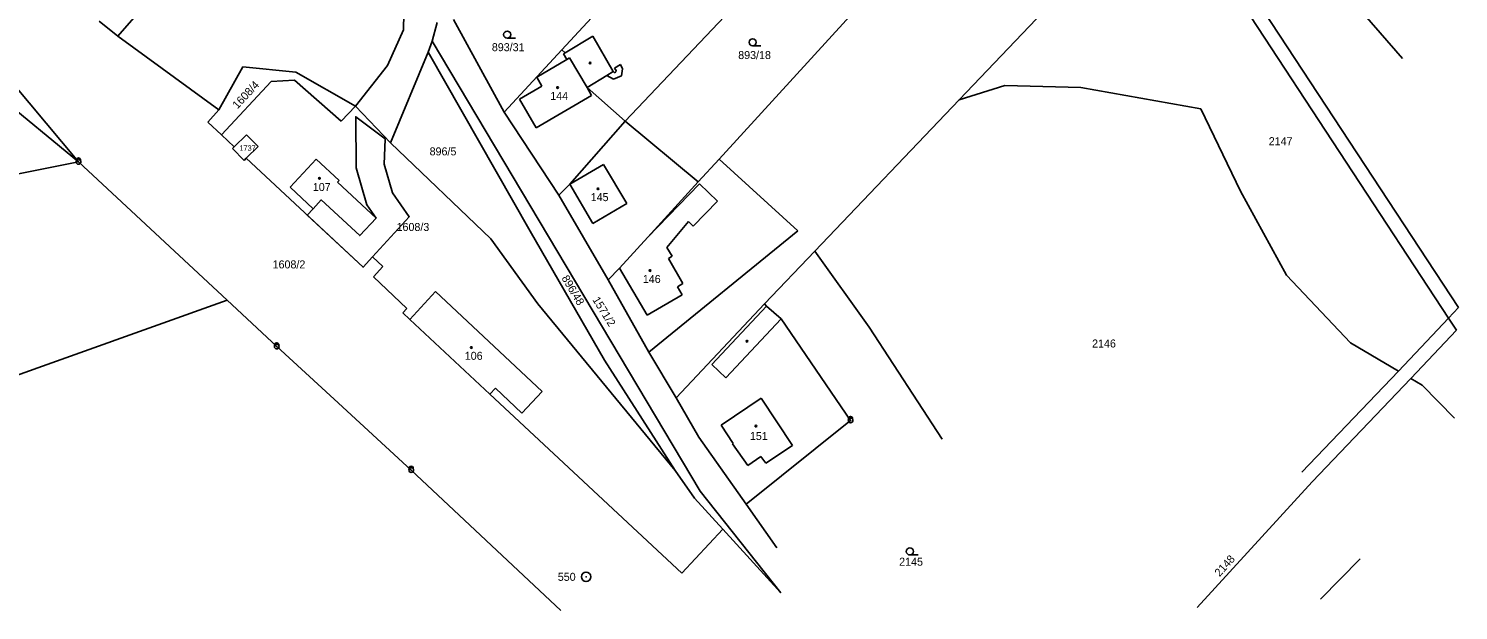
# Model space of a CAD drawing. Extents: x -801826 to -800592, y -1032871 to -1031813.
# Drawn here: x -800902.2 to -800598.5, y -1032871.4 to -1032747.9 of the extents above; entities that cross this region are included whole.
import ezdxf

# ---------------------------------------------------------------- set-up
doc = ezdxf.new("R2010")
doc.units = 0
for name, color, linetype in [('Vrstva 1', 7, 'Continuous'), ('Vrstva 17', 7, 'Continuous'), ('Vrstva 18', 7, 'Continuous'), ('Vrstva 19', 7, 'Continuous'), ('Vrstva 24', 7, 'Continuous'), ('Vrstva 25', 7, 'Continuous'), ('Vrstva 27', 7, 'Continuous'), ('Vrstva 4', 7, 'Continuous')]:
    doc.layers.add(name, color=color, linetype=linetype)

msp = doc.modelspace()

# ---------------------------------------------------------------- linework, layer by layer
at = {"layer": 'Vrstva 1'}
for p, q in [((-800685.05, -1032668.07), (-800610.32, -1032754.24)), ((-800974.29, -1032708.2), (-800891.58, -1032776.17)), ((-800891.58, -1032776.17), (-800936.91, -1032722.01)), ((-800704.52, -1032763.01), (-800666.33, -1032723)), ((-800862.89, -1032726), (-800883.21, -1032749.46)), ((-800775.49, -1032767.53), (-800739.93, -1032730.06)), ((-800822.52, -1032748.12), (-800822.34, -1032737.75)), ((-800719.34, -1032735.97), (-800755.52, -1032775.59)), ((-800598.47, -1032807.13), (-800641.5, -1032741.52)), ((-800779.9, -1032742.67), (-800788.9, -1032752.39)), ((-800600.58, -1032809.38), (-800644.04, -1032743.12)), ((-800883.21, -1032749.46), (-800887.16, -1032746.32)), ((-800816.49, -1032750.53), (-800815.39, -1032746.59)), ((-800801.15, -1032765.61), (-800811.93, -1032745.91)), ((-800883.21, -1032749.46), (-800861.74, -1032765.15)), ((-800825.94, -1032755.74), (-800822.52, -1032748.12)), ((-800817.28, -1032752.88), (-800816.49, -1032750.53)), ((-800759.53, -1032846.08), (-800816.49, -1032750.53)), ((-800788.23, -1032753.03), (-800782.33, -1032749.51)), ((-800782.33, -1032749.51), (-800778, -1032756.99)), ((-800825.32, -1032772.12), (-800817.28, -1032752.88)), ((-800795.62, -1032790.87), (-800817.28, -1032752.88)), ((-800788.9, -1032752.39), (-800801.15, -1032765.61)), ((-800788.23, -1032753.03), (-800788.9, -1032752.39)), ((-800861.74, -1032765.15), (-800856.65, -1032755.96)), ((-800856.65, -1032755.96), (-800845.4, -1032757.1)), ((-800832.71, -1032764.32), (-800825.94, -1032755.74)), ((-800776.46, -1032755.5), (-800777.71, -1032756.24)), ((-800777.71, -1032756.24), (-800777.39, -1032756.79)), ((-800776.02, -1032756.45), (-800776.46, -1032755.5)), ((-800776.25, -1032757.88), (-800776.02, -1032756.45)), ((-800861.23, -1032770.42), (-800850.67, -1032759.09)), ((-800850.67, -1032759.09), (-800845.69, -1032758.85)), ((-800845.69, -1032758.85), (-800835.76, -1032767.56)), ((-800845.4, -1032757.1), (-800832.71, -1032764.32)), ((-800783.54, -1032760.36), (-800779.32, -1032757.8)), ((-800779.32, -1032757.8), (-800777.91, -1032758.6)), ((-800777.72, -1032757.25), (-800778, -1032756.99)), ((-800777.91, -1032758.6), (-800776.25, -1032757.88)), ((-800777.41, -1032757.08), (-800777.72, -1032757.25)), ((-800777.39, -1032756.79), (-800777.41, -1032757.08)), ((-800775.49, -1032767.53), (-800783.54, -1032760.36)), ((-800694.83, -1032759.95), (-800704.52, -1032763.01)), ((-800678.69, -1032760.36), (-800694.83, -1032759.95)), ((-800653.15, -1032764.9), (-800678.69, -1032760.36)), ((-800861.74, -1032765.15), (-800864.13, -1032767.71)), ((-800835.76, -1032767.56), (-800832.71, -1032764.32)), ((-800832.71, -1032764.32), (-800825.32, -1032772.12)), ((-800801.15, -1032765.61), (-800789.53, -1032783.23)), ((-800735.19, -1032795.14), (-800704.52, -1032763.01)), ((-800644.79, -1032782.39), (-800653.15, -1032764.9)), ((-800864.13, -1032767.71), (-800861.23, -1032770.42)), ((-800787.2, -1032780.94), (-800775.49, -1032767.53)), ((-800759.94, -1032780.44), (-800775.49, -1032767.53)), ((-800861.23, -1032770.42), (-800858.49, -1032772.99)), ((-800858.49, -1032772.99), (-800855.86, -1032770.41)), ((-800853.41, -1032772.91), (-800855.86, -1032770.41)), ((-800858.86, -1032773.35), (-800858.49, -1032772.99)), ((-800858.86, -1032773.35), (-800856.41, -1032775.85)), ((-800853.41, -1032772.91), (-800855.93, -1032775.38)), ((-800825.32, -1032772.12), (-800803.96, -1032792.55)), ((-800891.58, -1032776.17), (-800918.55, -1032781.54)), ((-800891.58, -1032776.17), (-800860.02, -1032805.58)), ((-800855.93, -1032775.38), (-800856.41, -1032775.85)), ((-800855.93, -1032775.38), (-800831.14, -1032798.57)), ((-800846.61, -1032781.52), (-800841.09, -1032775.58)), ((-800836.18, -1032780.12), (-800841.09, -1032775.58)), ((-800755.52, -1032775.59), (-800759.94, -1032780.44)), ((-800738.81, -1032790.85), (-800755.52, -1032775.59)), ((-800836.53, -1032780.5), (-800836.18, -1032780.12)), ((-800828.38, -1032788.14), (-800836.53, -1032780.5)), ((-800789.53, -1032783.23), (-800787.2, -1032780.94)), ((-800770.63, -1032792.16), (-800759.94, -1032780.44)), ((-800846.61, -1032781.52), (-800841.71, -1032786.12)), ((-800779.08, -1032801.22), (-800789.53, -1032783.23)), ((-800634.97, -1032800.21), (-800644.79, -1032782.39)), ((-800841.71, -1032786.12), (-800840.04, -1032784.27)), ((-800840.04, -1032784.27), (-800831.83, -1032791.83)), ((-800831.83, -1032791.83), (-800828.38, -1032788.14)), ((-800803.96, -1032792.55), (-800794.02, -1032806.35)), ((-800779.82, -1032818.29), (-800795.62, -1032790.87)), ((-800776.64, -1032798.73), (-800770.63, -1032792.16)), ((-800770.44, -1032816.58), (-800738.81, -1032790.85)), ((-800745.85, -1032806.31), (-800735.19, -1032795.14)), ((-800723.65, -1032811.31), (-800735.19, -1032795.14)), ((-800831.14, -1032798.57), (-800829.12, -1032796.36)), ((-800829.12, -1032796.36), (-800826.93, -1032798.41)), ((-800826.93, -1032798.41), (-800828.95, -1032800.62)), ((-800776.64, -1032798.73), (-800779.08, -1032801.22)), ((-800828.95, -1032800.62), (-800821.81, -1032807.31)), ((-800779.08, -1032801.22), (-800770.44, -1032816.58)), ((-800621.36, -1032814.6), (-800634.97, -1032800.21)), ((-800815.75, -1032803.7), (-800821.22, -1032809.62)), ((-800815.75, -1032803.7), (-800793.1, -1032824.93)), ((-800860.02, -1032805.58), (-801002.86, -1032856.61)), ((-800860.02, -1032805.58), (-800849.48, -1032815.4)), ((-800821.81, -1032807.31), (-800822.69, -1032808.25)), ((-800822.69, -1032808.25), (-800821.22, -1032809.62)), ((-800794.02, -1032806.35), (-800764.86, -1032841.71)), ((-800745.85, -1032806.31), (-800764.65, -1032826.32)), ((-800745.41, -1032806.81), (-800745.85, -1032806.31)), ((-800742.33, -1032809.53), (-800745.41, -1032806.81)), ((-800600.58, -1032809.38), (-800598.47, -1032807.13)), ((-800821.22, -1032809.62), (-800804.24, -1032825.48)), ((-800727.58, -1032831.07), (-800742.33, -1032809.53)), ((-800708.13, -1032835.06), (-800723.65, -1032811.31)), ((-800605.22, -1032814.32), (-800600.58, -1032809.38)), ((-800598.87, -1032811.95), (-800600.58, -1032809.38)), ((-800611.2, -1032820.59), (-800605.22, -1032814.32)), ((-800608.56, -1032822.15), (-800598.87, -1032811.95)), ((-800849.48, -1032815.4), (-800837.28, -1032826.6)), ((-800764.65, -1032826.32), (-800770.44, -1032816.58)), ((-800611.2, -1032820.59), (-800621.36, -1032814.6)), ((-800764.86, -1032841.71), (-800779.82, -1032818.29)), ((-800631.71, -1032842.08), (-800611.2, -1032820.59)), ((-800629.52, -1032844.13), (-800608.56, -1032822.15)), ((-800606.15, -1032823.57), (-800608.56, -1032822.15)), ((-800804.24, -1032825.48), (-800803.03, -1032824.25)), ((-800804.24, -1032825.48), (-800763.43, -1032863.52)), ((-800797.41, -1032829.54), (-800803.03, -1032824.25)), ((-800793.1, -1032824.93), (-800797.41, -1032829.54)), ((-800759.81, -1032834.67), (-800764.65, -1032826.32)), ((-800599.28, -1032830.62), (-800606.15, -1032823.57)), ((-800837.28, -1032826.6), (-800820.91, -1032841.63)), ((-800749.79, -1032848.89), (-800727.58, -1032831.07)), ((-800749.79, -1032848.89), (-800759.81, -1032834.67)), ((-800820.91, -1032841.63), (-800789.16, -1032871.43)), ((-800764.86, -1032841.71), (-800760.73, -1032847.6)), ((-800653.99, -1032870.82), (-800629.52, -1032844.13)), ((-800760.73, -1032847.6), (-800754.72, -1032854.18)), ((-800742.38, -1032867.73), (-800759.53, -1032846.08)), ((-800743.22, -1032858.16), (-800749.79, -1032848.89)), ((-800763.43, -1032863.52), (-800754.72, -1032854.18)), ((-800754.72, -1032854.18), (-800742.38, -1032867.73)), ((-800627.73, -1032869.02), (-800619.37, -1032860.45))]:
    msp.add_line(p, q, dxfattribs=at)
at = {"layer": 'Vrstva 24'}
for centre, radius in [((-800891.58, -1032776.17), 0.5), ((-800891.58, -1032776.17), 0.0364), ((-800849.48, -1032815.4), 0.5), ((-800849.48, -1032815.4), 0.0364), ((-800727.58, -1032831.07), 0.5), ((-800727.58, -1032831.07), 0.0364), ((-800820.91, -1032841.63), 0.5), ((-800820.91, -1032841.63), 0.0364), ((-800783.75, -1032864.3), 1), ((-800783.75, -1032864.3), 0.0439)]:
    msp.add_circle(centre, radius, dxfattribs=at)
for centre in [(-800891.58, -1032775.8), (-800849.48, -1032815.03), (-800727.58, -1032830.7), (-800820.91, -1032841.26)]:
    msp.add_arc(centre, 0.45, 344.4473, 196.3778, dxfattribs=at)
at = {"layer": 'Vrstva 25'}
for p, q in [((-800798.77, -1032749.91), (-800800.52, -1032749.91)), ((-800746.63, -1032751.53), (-800748.38, -1032751.53)), ((-800713.24, -1032859.66), (-800714.99, -1032859.66))]:
    msp.add_line(p, q, dxfattribs=at)
for centre, radius in [((-800800.52, -1032749.16), 0.75), ((-800748.38, -1032750.78), 0.75), ((-800782.9, -1032755.17), 0.175), ((-800789.83, -1032760.39), 0.175), ((-800840.4, -1032779.68), 0.175), ((-800781.24, -1032781.9), 0.175), ((-800770.19, -1032799.25), 0.175), ((-800749.57, -1032814.26), 0.175), ((-800808.14, -1032815.61), 0.175), ((-800747.69, -1032832.3), 0.175), ((-800714.99, -1032858.91), 0.75)]:
    msp.add_circle(centre, radius, dxfattribs=at)
at = {"layer": 'Vrstva 27'}
for points in [[(-800832.6, -1032777.42), (-800832.68, -1032766.6), (-800826.45, -1032771.28)], [(-800826.45, -1032771.28), (-800826.47, -1032771.34), (-800826.63, -1032776.68), (-800824.91, -1032782.73), (-800821.33, -1032787.83), (-800829.12, -1032796.36), (-800831.14, -1032798.57), (-800842.99, -1032787.49)], [(-800842.99, -1032787.49), (-800841.71, -1032786.12), (-800840.04, -1032784.27), (-800831.83, -1032791.83), (-800828.38, -1032788.14), (-800830.36, -1032785.32), (-800832.6, -1032777.42)]]:
    msp.add_lwpolyline(points, dxfattribs=at)
at = {"layer": 'Vrstva 4'}
for p, q in [((-800788.58, -1032753.24), (-800788.23, -1032753.03)), ((-800787.86, -1032754.41), (-800788.58, -1032753.24)), ((-800794.2, -1032758.16), (-800787.86, -1032754.41)), ((-800787.28, -1032754.08), (-800787.86, -1032754.41)), ((-800783.54, -1032760.36), (-800787.28, -1032754.08)), ((-800793.14, -1032760.1), (-800794.2, -1032758.16)), ((-800779.32, -1032757.8), (-800778, -1032756.99)), ((-800797.9, -1032762.87), (-800793.14, -1032760.1)), ((-800794.33, -1032768.95), (-800782.59, -1032762.08)), ((-800782.59, -1032762.08), (-800783.54, -1032760.36)), ((-800794.33, -1032768.95), (-800797.9, -1032762.87)), ((-800780.04, -1032776.73), (-800787.2, -1032780.94)), ((-800775.14, -1032785.05), (-800780.04, -1032776.73)), ((-800782.3, -1032789.26), (-800787.2, -1032780.94)), ((-800770.63, -1032792.16), (-800759.7, -1032780.82)), ((-800759.7, -1032780.82), (-800755.88, -1032784.5)), ((-800782.3, -1032789.26), (-800775.14, -1032785.05)), ((-800755.88, -1032784.5), (-800761.02, -1032789.83)), ((-800762.03, -1032788.86), (-800766.59, -1032794.34)), ((-800761.02, -1032789.83), (-800762.03, -1032788.86)), ((-800765.51, -1032796.23), (-800766.59, -1032794.34)), ((-800770.8, -1032808.71), (-800776.64, -1032798.73)), ((-800766.29, -1032796.68), (-800765.51, -1032796.23)), ((-800763.22, -1032802.04), (-800766.29, -1032796.68)), ((-800764.34, -1032802.68), (-800763.22, -1032802.04)), ((-800763.33, -1032804.44), (-800770.8, -1032808.71)), ((-800763.33, -1032804.44), (-800764.34, -1032802.68)), ((-800757.07, -1032819.2), (-800745.41, -1032806.81)), ((-800742.33, -1032809.53), (-800754.09, -1032822.01)), ((-800754.09, -1032822.01), (-800757.07, -1032819.2)), ((-800755.04, -1032832.11), (-800746.57, -1032826.38)), ((-800739.94, -1032836.38), (-800746.57, -1032826.38)), ((-800755.04, -1032832.11), (-800752.49, -1032835.98)), ((-800752.49, -1032835.98), (-800752.66, -1032836.09)), ((-800752.66, -1032836.09), (-800749.39, -1032840.69)), ((-800749.39, -1032840.69), (-800746.62, -1032838.72)), ((-800746.62, -1032838.72), (-800745.58, -1032840.19)), ((-800745.58, -1032840.19), (-800739.94, -1032836.38))]:
    msp.add_line(p, q, dxfattribs=at)

# ---------------------------------------------------------------- texts
at = {"layer": 'Vrstva 17'}
msp.add_text('550', height=1.7, dxfattribs=at).set_placement((-800789.77, -1032865.15))
at = {"layer": 'Vrstva 18'}
for s, height, p in [('893/31', 1.7, (-800803.78, -1032752.67)), ('893/18', 1.7, (-800751.45, -1032754.34)), ('2147', 1.7, (-800638.76, -1032772.63)), ('1737', 1.14, (-800857.42, -1032773.82)), ('896/5', 1.7, (-800817, -1032774.8)), ('1608/3', 1.7, (-800824.02, -1032790.85)), ('1608/2', 1.7, (-800850.35, -1032798.8)), ('2146', 1.7, (-800676.28, -1032815.6)), ('2145', 1.7, (-800717.26, -1032861.94))]:
    msp.add_text(s, height=height, dxfattribs=at).set_placement(p)
for s, rotation, p in [('1608/4', 46.6961, (-800857.82, -1032765.04)), ('896/48', 300.7355, (-800789.04, -1032800.87)), ('1571/2', 301.9319, (-800782.49, -1032805.45)), ('2148', 47.8993, (-800649.19, -1032864.38))]:
    msp.add_text(s, height=1.7, rotation=rotation, dxfattribs=at).set_placement(p)
at = {"layer": 'Vrstva 19'}
for s, p in [('144', (-800791.38, -1032763.03)), ('107', (-800841.81, -1032782.36)), ('145', (-800782.78, -1032784.51)), ('146', (-800771.71, -1032801.9)), ('106', (-800809.53, -1032818.21)), ('151', (-800748.97, -1032835.24))]:
    msp.add_text(s, height=1.7, dxfattribs=at).set_placement(p)

doc.saveas('drawing.dxf')
